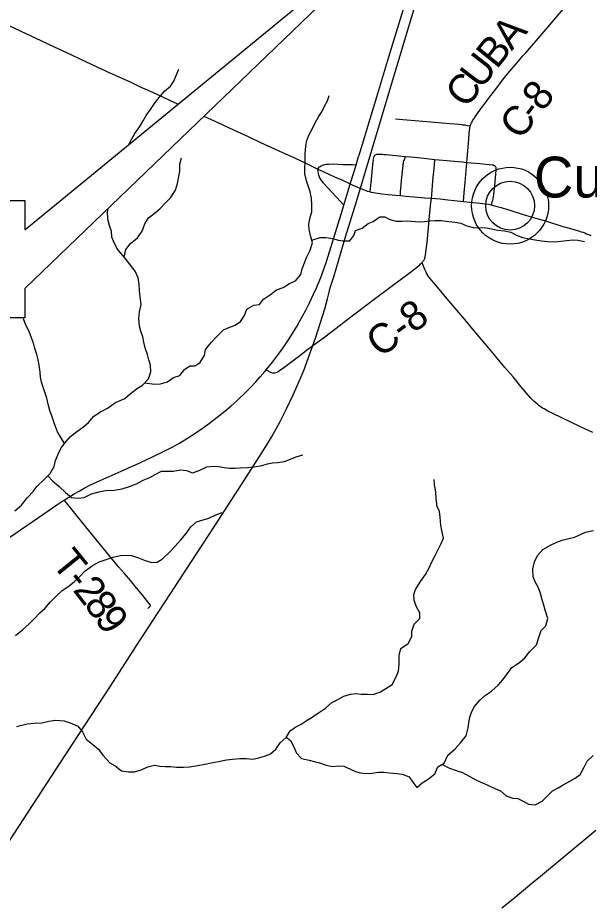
# Model space of a CAD drawing. Extents: x 0 to 34, y 0 to 22.
# Drawn here: x 4.732 to 5.838, y 15.651 to 17.368 of the extents above; entities that cross this region are included whole.
import ezdxf

# ---------------------------------------------------------------- set-up
doc = ezdxf.new("R2010")
doc.units = 0
for name, color, linetype in [('GM_X_County_Road', 7, 'Continuous'), ('GM_X_County_Road_Text', 7, 'Continuous'), ('GM_X_Minor_River', 7, 'Continuous'), ('GM_X_Rail_Line', 7, 'Continuous'), ('GM_X_State_Route', 7, 'Continuous'), ('GM_X_Township_Road', 7, 'Continuous'), ('GM_X_Township_Road_Text', 7, 'Continuous'), ('GM_X_Unincorporated', 7, 'Continuous'), ('GM_X_Unincorporated_Location', 7, 'Continuous'), ('GM_X_Unincorporated_Text', 7, 'Continuous'), ('GM_X_US_Route', 7, 'Continuous'), ('SH_Text', 7, 'Continuous')]:
    doc.layers.add(name, color=color, linetype=linetype)

msp = doc.modelspace()

# ---------------------------------------------------------------- linework, layer by layer
at = {"layer": 'GM_X_County_Road'}
for points in [[(5.6077, 17.1586), (5.608, 17.1598), (5.6085, 17.161), (5.609, 17.1621), (5.6095, 17.1632), (5.6101, 17.1646), (5.6111, 17.1662), (5.6122, 17.1683), (5.6133, 17.1699), (5.6146, 17.172), (5.6157, 17.1737), (5.6167, 17.1751), (5.6265, 17.1887), (5.6476, 17.2172), (5.6588, 17.2321), (5.674, 17.2518), (5.6842, 17.2642), (5.6962, 17.2783), (5.7097, 17.2937), (5.7151, 17.2997), (5.7466, 17.3365), (5.7884, 17.3849)], [(5.601, 17.0878), (5.6047, 17.1322), (5.6057, 17.1441), (5.6069, 17.1534), (5.6071, 17.1553), (5.6074, 17.1572), (5.6077, 17.1586)], [(5.5943, 17.0123), (5.5958, 17.0291), (5.5977, 17.0488), (5.601, 17.0878)], [(5.5143, 16.8938), (5.5153, 16.8952), (5.5164, 16.8967), (5.5174, 16.8982), (5.5184, 16.8995), (5.519, 16.9008), (5.5197, 16.9025), (5.5202, 16.9042), (5.5205, 16.9058), (5.5209, 16.908), (5.5225, 16.9192), (5.5242, 16.9328), (5.5295, 16.9909), (5.5314, 17.0096), (5.5325, 17.0184)], [(5.5325, 17.0184), (5.5496, 17.0171), (5.5644, 17.0157), (5.5885, 17.0128), (5.5943, 17.0123)], [(5.2129, 16.6865), (5.2213, 16.6819), (5.2231, 16.6812), (5.2251, 16.6807), (5.2271, 16.6806), (5.2298, 16.6808), (5.2323, 16.6815), (5.2352, 16.6828), (5.2394, 16.6855), (5.244, 16.6888), (5.2495, 16.6929), (5.2575, 16.699), (5.2753, 16.7125), (5.2936, 16.7265), (5.3021, 16.7327), (5.326, 16.7506), (5.3479, 16.7671), (5.3681, 16.7825), (5.4241, 16.8249), (5.4774, 16.8646), (5.4894, 16.8736), (5.5027, 16.8838), (5.51, 16.8897), (5.5117, 16.8913), (5.5133, 16.8927), (5.5143, 16.8938)], [(5.8446, 16.5652), (5.8199, 16.577), (5.7676, 16.6017), (5.7576, 16.6068), (5.7505, 16.6108), (5.7476, 16.6126), (5.7447, 16.6144), (5.7412, 16.617), (5.7382, 16.6193), (5.7349, 16.6222), (5.7316, 16.6251), (5.7283, 16.6284), (5.725, 16.6318), (5.7167, 16.6411), (5.7055, 16.6544), (5.6904, 16.6726), (5.6748, 16.6911), (5.6566, 16.7131), (5.6437, 16.7283), (5.6185, 16.7582), (5.5969, 16.7839), (5.574, 16.811), (5.5633, 16.8238), (5.544, 16.8465), (5.5332, 16.8594), (5.5269, 16.8672), (5.5248, 16.8703), (5.523, 16.8737), (5.5215, 16.8769), (5.5199, 16.8805), (5.5143, 16.8938)]]:
    msp.add_lwpolyline(points, dxfattribs=at)
at = {"layer": 'GM_X_Minor_River'}
for points in [[(4.9475, 17.1231), (4.9495, 17.1279), (4.9584, 17.1437), (4.9685, 17.1572), (4.9747, 17.1685), (4.9805, 17.1787), (4.9891, 17.1904), (4.998, 17.2035), (5.0057, 17.2133), (5.0169, 17.2261), (5.0276, 17.2354), (5.0338, 17.2452), (5.0385, 17.2558), (5.0437, 17.2682)], [(4.9776, 16.6613), (4.9963, 16.6588), (5.0081, 16.6591), (5.0218, 16.6631), (5.0333, 16.6713), (5.0455, 16.6753), (5.0548, 16.6873), (5.0652, 16.694), (5.0747, 16.6943), (5.0842, 16.7002), (5.0932, 16.7145), (5.0956, 16.7259), (5.1072, 16.7398), (5.1168, 16.7503), (5.1299, 16.7638), (5.1421, 16.7689), (5.1528, 16.773), (5.1628, 16.7797), (5.1705, 16.7913), (5.1753, 16.8038), (5.1887, 16.8116), (5.1997, 16.8126), (5.2074, 16.8235), (5.2212, 16.8321), (5.2328, 16.8414), (5.2454, 16.8458), (5.2576, 16.8532), (5.2694, 16.8584), (5.2795, 16.8708), (5.2827, 16.8821), (5.287, 16.8938), (5.2906, 16.904), (5.298, 16.918), (5.3024, 16.9324), (5.2991, 16.9438), (5.2962, 16.9579), (5.2956, 16.9685), (5.2981, 16.981), (5.3013, 16.992), (5.3014, 17.0056), (5.3005, 17.0182), (5.2976, 17.0311), (5.2947, 17.0406), (5.291, 17.0521), (5.2874, 17.0654), (5.2876, 17.0768), (5.2881, 17.0882), (5.2879, 17.1037), (5.2893, 17.1197), (5.2913, 17.1303), (5.2953, 17.1405), (5.3031, 17.1544), (5.3078, 17.1642), (5.314, 17.1759), (5.3202, 17.1857), (5.3257, 17.1966), (5.3311, 17.2068), (5.3347, 17.2174)], [(4.938, 16.9043), (4.9413, 16.9192), (4.9502, 16.9308), (4.964, 16.9417), (4.9726, 16.9549), (4.9777, 16.9688), (4.9851, 16.9805), (4.9951, 16.9883), (5.007, 16.9981), (5.0178, 17.0097), (5.0274, 17.019), (5.0375, 17.0341), (5.0414, 17.047), (5.0431, 17.0576), (5.0456, 17.0708), (5.0457, 17.0841), (5.0486, 17.0966)], [(4.9065, 16.9987), (4.9049, 16.9923), (4.9058, 16.9786), (4.9091, 16.9664), (4.9127, 16.955), (4.9137, 16.9436), (4.9188, 16.9317), (4.9243, 16.9203)], [(5.3009, 16.9374), (5.3173, 16.9424), (5.3279, 16.9427), (5.342, 16.9406), (5.3518, 16.9374), (5.3613, 16.9358), (5.3749, 16.936), (5.3823, 16.9461), (5.3859, 16.956), (5.3988, 16.9603), (5.4103, 16.9693), (5.4199, 16.9734), (5.4329, 16.9823), (5.4424, 16.9822), (5.4522, 16.9775), (5.464, 16.9743), (5.4757, 16.9741), (5.4856, 16.9748), (5.5091, 16.973), (5.519, 16.9736), (5.5293, 16.9746), (5.5396, 16.9752), (5.5513, 16.9754), (5.5665, 16.9734), (5.5779, 16.9721), (5.5892, 16.97), (5.601, 16.9653), (5.6157, 16.9613), (5.6286, 16.9619), (5.6389, 16.961), (5.6487, 16.9594), (5.6601, 16.9566), (5.6738, 16.9553), (5.6863, 16.9528), (5.6972, 16.947), (5.7085, 16.9423), (5.7225, 16.9398), (5.7331, 16.9378), (5.7453, 16.9361), (5.7574, 16.9348), (5.7707, 16.9343), (5.7943, 16.937), (5.8057, 16.938), (5.8156, 16.9371), (5.8288, 16.9347)], [(4.9209, 16.623), (4.9394, 16.6311), (4.9493, 16.6397), (4.9639, 16.6513), (4.9735, 16.6569), (4.9847, 16.6689), (4.9894, 16.6828), (4.9888, 16.6954), (4.9859, 16.7057), (4.983, 16.7163), (4.9787, 16.7289), (4.9761, 16.7403), (4.974, 16.7506), (4.97, 16.7613), (4.9674, 16.7712), (4.9665, 16.7856), (4.9674, 16.7985), (4.971, 16.8129), (4.969, 16.827), (4.9676, 16.8399), (4.967, 16.8513), (4.9649, 16.8642), (4.9594, 16.8772), (4.9504, 16.8891), (4.9418, 16.8998), (4.9243, 16.9203)], [(4.8227, 16.5437), (4.8166, 16.5535), (4.8092, 16.5665), (4.8034, 16.5818), (4.7986, 16.5955), (4.7943, 16.6077), (4.7914, 16.6176), (4.7882, 16.6317), (4.7849, 16.6412), (4.7813, 16.6527), (4.778, 16.6626), (4.7762, 16.6721), (4.7752, 16.682), (4.7735, 16.6957), (4.7718, 16.7059), (4.7689, 16.7162), (4.7653, 16.7277), (4.7624, 16.7383), (4.7588, 16.7483), (4.754, 16.7605), (4.7477, 16.7727), (4.743, 16.7849)], [(4.7262, 16.4139), (4.7393, 16.4247), (4.7501, 16.4386), (4.7617, 16.4513), (4.7698, 16.4611), (4.7832, 16.4742), (4.7948, 16.4858), (4.8025, 16.4994), (4.805, 16.5111), (4.8105, 16.5232), (4.8163, 16.5353), (4.8256, 16.5477), (4.8341, 16.5574), (4.8464, 16.5671), (4.859, 16.5764), (4.8686, 16.5843), (4.8794, 16.5967), (4.8924, 16.6052), (4.9054, 16.6123), (4.9209, 16.623)], [(4.9183, 16.4534), (4.934, 16.4562), (4.9485, 16.4609), (4.9618, 16.4661), (4.9748, 16.4727), (4.9874, 16.4783), (4.9978, 16.4842), (5.0104, 16.4901), (5.0214, 16.4904), (5.0328, 16.4906), (5.0469, 16.4927), (5.0586, 16.4914), (5.07, 16.4874), (5.0833, 16.4914), (5.0979, 16.4988), (5.1112, 16.5002), (5.121, 16.4997), (5.1316, 16.4977), (5.1419, 16.496), (5.1525, 16.4962), (5.1624, 16.4969), (5.1768, 16.4974), (5.1886, 16.4988), (5.202, 16.5009), (5.2153, 16.5045), (5.2252, 16.5063), (5.2347, 16.5069), (5.248, 16.5091), (5.2599, 16.5138), (5.2706, 16.5182), (5.2835, 16.5219)], [(4.7904, 16.4814), (4.7999, 16.4709), (4.8122, 16.4605), (4.8242, 16.449), (4.8362, 16.4397), (4.8491, 16.4384), (4.8608, 16.4397), (4.875, 16.4468), (4.8887, 16.4504), (4.902, 16.4529), (4.9183, 16.4534)], [(4.9103, 15.9258), (4.9207, 15.9204), (4.9327, 15.9103), (4.9463, 15.9086), (4.9577, 15.9085), (4.9711, 15.9125), (4.9837, 15.9184), (4.9963, 15.9213), (5.0069, 15.9196), (5.0171, 15.9191), (5.0278, 15.919), (5.0391, 15.9177), (5.0528, 15.9179), (5.0642, 15.9185), (5.0802, 15.9206), (5.0939, 15.9234), (5.1061, 15.9259), (5.1202, 15.9288), (5.1362, 15.932), (5.1476, 15.9334), (5.1617, 15.9347), (5.1746, 15.9345), (5.186, 15.9329), (5.1959, 15.935), (5.2096, 15.939), (5.2214, 15.9434), (5.2314, 15.9524), (5.2396, 15.9648), (5.2511, 15.9753), (5.2592, 15.9881), (5.27, 15.9955), (5.2803, 16.0007), (5.2903, 16.0071), (5.3037, 16.0156), (5.3159, 16.0238), (5.3274, 16.032), (5.3401, 16.0425), (5.3512, 16.0488), (5.3627, 16.0551), (5.3757, 16.0587), (5.3871, 16.0605), (5.3966, 16.0592), (5.4091, 16.0587), (5.4201, 16.0581), (5.4342, 16.0633), (5.4442, 16.07), (5.4568, 16.0778), (5.4642, 16.0925), (5.4689, 16.1034), (5.4699, 16.1179), (5.4701, 16.1338), (5.4733, 16.1474), (5.4875, 16.1571), (5.4949, 16.1707), (5.4947, 16.1809), (5.499, 16.1942), (5.5102, 16.205), (5.5103, 16.216), (5.5033, 16.2294), (5.4989, 16.2408), (5.4983, 16.2515), (5.5018, 16.2617), (5.5115, 16.2771), (5.5212, 16.2907), (5.5279, 16.3035), (5.5337, 16.3163), (5.5403, 16.3284), (5.5458, 16.3386), (5.5513, 16.3502), (5.556, 16.3608), (5.5524, 16.3753), (5.5506, 16.3856), (5.5497, 16.4011), (5.5479, 16.4122), (5.5439, 16.4221), (5.5418, 16.4369), (5.5408, 16.4506), (5.5384, 16.4639), (5.5381, 16.4742)], [(4.9164, 16.3243), (4.9311, 16.3275), (4.9429, 16.3281), (4.9523, 16.3269), (4.9656, 16.3229), (4.9784, 16.3178), (4.9913, 16.3135), (5.0016, 16.3145), (5.0123, 16.3208), (5.0269, 16.335), (5.0361, 16.3448), (5.0477, 16.3575), (5.0578, 16.3695), (5.0667, 16.3827), (5.0778, 16.3921), (5.0908, 16.3964), (5.1015, 16.3997), (5.1156, 16.406), (5.1278, 16.4104)], [(5.2515, 15.976), (5.2598, 15.9695), (5.2664, 15.9569), (5.2716, 15.9447), (5.2813, 15.9347), (5.2957, 15.9314), (5.3059, 15.9287), (5.3158, 15.9259), (5.3267, 15.9219), (5.3404, 15.9191), (5.3529, 15.9201), (5.3628, 15.9196), (5.3756, 15.9137), (5.3854, 15.909), (5.3953, 15.9066), (5.4051, 15.9057), (5.4169, 15.906), (5.4298, 15.9077), (5.4405, 15.9079), (5.4515, 15.907), (5.4659, 15.9053), (5.4761, 15.9044), (5.4894, 15.8989), (5.4964, 15.8886), (5.5043, 15.8783), (5.5146, 15.8872), (5.5261, 15.8947), (5.5388, 15.9048), (5.5451, 15.918), (5.5569, 15.9254), (5.564, 15.9409), (5.5786, 15.9532), (5.589, 15.9648), (5.5998, 15.978), (5.6034, 15.9939), (5.6051, 16.0037), (5.6068, 16.0143), (5.6099, 16.0242), (5.6162, 16.0351), (5.6262, 16.0471), (5.6373, 16.0572), (5.6485, 16.0647), (5.6619, 16.0766), (5.6704, 16.0864), (5.6781, 16.0962), (5.6882, 16.1108), (5.7028, 16.1205), (5.7131, 16.1295), (5.7232, 16.1415), (5.7359, 16.1543), (5.7403, 16.1686), (5.7446, 16.1819), (5.7542, 16.1912), (5.7575, 16.2056), (5.7524, 16.2212), (5.7498, 16.2308), (5.7469, 16.2414), (5.7437, 16.2536), (5.7397, 16.2647), (5.7334, 16.2761), (5.7297, 16.2861), (5.7288, 16.3016), (5.732, 16.3149), (5.7378, 16.3273), (5.7479, 16.3386), (5.7628, 16.3471), (5.7754, 16.353), (5.7853, 16.3567), (5.7987, 16.3603), (5.8093, 16.3629), (5.8212, 16.3676), (5.8307, 16.3724), (5.8464, 16.3757)], [(4.7276, 16.1724), (4.7411, 16.1836), (4.7541, 16.1952), (4.7638, 16.2049), (4.7749, 16.2162), (4.7845, 16.2248), (4.7953, 16.2375), (4.8061, 16.2488), (4.818, 16.2596), (4.8287, 16.2667), (4.8414, 16.2764), (4.851, 16.285), (4.8622, 16.2974), (4.8763, 16.307), (4.8897, 16.3152), (4.8993, 16.3185), (4.9164, 16.3243)], [(4.73, 15.9966), (4.7399, 15.9987), (4.7502, 16.0016), (4.7635, 16.003), (4.7783, 16.0032), (4.792, 16.0064), (4.8053, 16.0089), (4.8219, 16.0075), (4.8333, 16.0035), (4.8483, 15.9969), (4.8573, 15.9858), (4.8646, 15.972), (4.8774, 15.9616), (4.8883, 15.9527), (4.8968, 15.9412), (4.9103, 15.9258)], [(5.5532, 15.9231), (5.5678, 15.9158), (5.5822, 15.9103), (5.5924, 15.9071), (5.6056, 15.9001), (5.6173, 15.8939), (5.6282, 15.8888), (5.6414, 15.8826), (5.655, 15.8763), (5.666, 15.872), (5.6769, 15.862), (5.6901, 15.858), (5.7, 15.8571), (5.7102, 15.8517), (5.7207, 15.8458), (5.7336, 15.8445), (5.7466, 15.852), (5.757, 15.8625), (5.767, 15.8722), (5.7777, 15.8774), (5.7873, 15.8833), (5.8003, 15.8907), (5.811, 15.8967), (5.8206, 15.9038), (5.8284, 15.9177), (5.8339, 15.929), (5.8454, 15.9403)]]:
    msp.add_lwpolyline(points, dxfattribs=at)
at = {"layer": 'GM_X_Rail_Line'}
msp.add_lwpolyline([(4.6156, 15.6215), (4.8241, 15.9416), (4.9114, 16.0746), (4.9613, 16.1518), (5.1119, 16.3828), (5.1792, 16.4864), (5.2122, 16.5384), (5.2228, 16.5564), (5.239, 16.5855), (5.2512, 16.6096), (5.2649, 16.6381), (5.2772, 16.6659), (5.2853, 16.685), (5.2949, 16.71), (5.309, 16.7496), (5.3263, 16.8047), (5.3317, 16.8237), (5.3347, 16.8369), (5.3368, 16.8453), (5.3438, 16.8662), (5.3662, 16.9437), (5.3876, 17.012), (5.4635, 17.2672), (5.5484, 17.5486)], dxfattribs=at)
at = {"layer": 'GM_X_State_Route'}
msp.add_line((5.3754, 17.0462), (5.382, 17.0433), dxfattribs=at)
for points in [[(4.6811, 17.3682), (4.7112, 17.3543), (4.7144, 17.3528), (4.7475, 17.337), (4.7768, 17.3234), (4.8026, 17.3112), (4.8263, 17.3003), (4.8617, 17.2836), (4.8866, 17.2723), (4.9103, 17.2614), (4.9493, 17.2435), (4.9689, 17.2342), (4.9927, 17.2234), (5.0118, 17.2144), (5.0259, 17.208), (5.0422, 17.2007)], [(5.0924, 17.1773), (5.1189, 17.1648), (5.1494, 17.1508), (5.1781, 17.1376), (5.2018, 17.1266), (5.2215, 17.1173), (5.2446, 17.1067), (5.2661, 17.097), (5.2892, 17.0863), (5.3129, 17.0748), (5.324, 17.0698), (5.3449, 17.0601), (5.3591, 17.0538), (5.3754, 17.0462)], [(5.3129, 17.0748), (5.3124, 17.0724), (5.3124, 17.0703), (5.3131, 17.0662), (5.3139, 17.0637), (5.3144, 17.0618), (5.3162, 17.058), (5.3172, 17.0563), (5.3192, 17.0531), (5.323, 17.0482), (5.3322, 17.0383), (5.3568, 17.0121), (5.3631, 17.0053)], [(5.382, 17.0433), (5.3895, 17.0399), (5.3972, 17.0369), (5.4021, 17.0348), (5.4054, 17.0335), (5.4082, 17.0324), (5.4123, 17.0313), (5.4137, 17.0309), (5.4162, 17.0302), (5.4202, 17.0294), (5.4243, 17.0288), (5.4289, 17.0281), (5.4364, 17.0272), (5.4488, 17.0257), (5.4717, 17.0237), (5.4727, 17.0236), (5.4834, 17.0226), (5.4982, 17.0211), (5.5199, 17.0194), (5.5325, 17.0184)], [(5.5325, 17.0184), (5.5496, 17.0171), (5.5644, 17.0157), (5.5885, 17.0128), (5.5943, 17.0123)], [(5.5943, 17.0123), (5.607, 17.0111), (5.6268, 17.009), (5.6358, 17.0077), (5.6427, 17.0068), (5.6482, 17.0057), (5.6489, 17.0055), (5.6548, 17.004), (5.6619, 17.0021), (5.6682, 17.0003)], [(5.6682, 17.0003), (5.6691, 17.0001), (5.6786, 16.9973), (5.694, 16.9924), (5.7165, 16.9852), (5.7391, 16.9786), (5.7552, 16.9738), (5.7866, 16.9638), (5.8016, 16.9597), (5.8171, 16.9554), (5.8223, 16.9537), (5.8259, 16.9526), (5.8292, 16.9513), (5.8328, 16.9499), (5.8364, 16.9483), (5.8407, 16.9463)]]:
    msp.add_lwpolyline(points, dxfattribs=at)
at = {"layer": 'GM_X_Township_Road'}
for points in [[(5.4631, 17.1723), (5.4773, 17.1711), (5.5311, 17.1666), (5.5601, 17.1639), (5.5854, 17.1616), (5.5912, 17.1611), (5.5932, 17.1608), (5.5952, 17.1606), (5.5971, 17.1603), (5.5993, 17.16), (5.602, 17.1595), (5.6077, 17.1586)], [(5.4233, 17.1017), (5.4242, 17.1025), (5.4254, 17.1032), (5.4267, 17.1036), (5.4308, 17.1038), (5.4338, 17.1038), (5.4376, 17.1037), (5.4413, 17.1034), (5.445, 17.1031), (5.4823, 17.0994)], [(5.4137, 17.0309), (5.4144, 17.0375), (5.4165, 17.0553), (5.4191, 17.0837), (5.4203, 17.093), (5.4211, 17.0979), (5.4214, 17.0989), (5.4218, 17.0998), (5.4226, 17.1008), (5.4233, 17.1017)], [(5.4727, 17.0236), (5.4728, 17.0261), (5.4728, 17.0287), (5.4729, 17.0328), (5.473, 17.0361), (5.4744, 17.0527), (5.4778, 17.0816), (5.4781, 17.0838), (5.4784, 17.0859), (5.4788, 17.0883), (5.4793, 17.0907), (5.4801, 17.093), (5.4823, 17.0994)], [(5.4823, 17.0994), (5.4925, 17.0984), (5.5054, 17.0971), (5.5184, 17.0957), (5.5391, 17.0937)], [(5.5325, 17.0184), (5.5331, 17.0251), (5.5355, 17.0522), (5.5382, 17.0826), (5.5391, 17.0937)], [(5.5391, 17.0937), (5.5925, 17.0886), (5.601, 17.0878)], [(5.601, 17.0878), (5.6265, 17.0855), (5.6499, 17.0831), (5.6517, 17.0828), (5.6528, 17.0825), (5.6536, 17.0821), (5.6544, 17.0817)], [(5.6489, 17.0055), (5.6503, 17.0115), (5.6511, 17.0148), (5.6517, 17.0175), (5.6524, 17.0219), (5.653, 17.0255), (5.6551, 17.0433), (5.6577, 17.0729), (5.6578, 17.076), (5.6577, 17.0769), (5.6575, 17.0779), (5.6571, 17.0789), (5.6567, 17.0796), (5.6559, 17.0806), (5.6552, 17.0812), (5.6544, 17.0817)], [(4.9839, 16.2249), (4.9879, 16.2283), (4.9885, 16.229), (4.9889, 16.2296), (4.9889, 16.2307), (4.9886, 16.2313), (4.9881, 16.2319), (4.9856, 16.2353), (4.9738, 16.2497), (4.9647, 16.2607), (4.9628, 16.2631), (4.9623, 16.2636), (4.9505, 16.278), (4.9383, 16.2921), (4.9271, 16.3054), (4.9039, 16.3338), (4.8639, 16.3828), (4.8262, 16.429), (4.8217, 16.4345)], [(5.6689, 15.6452), (5.6904, 15.6628), (5.7271, 15.6935), (5.7434, 15.7069), (5.7894, 15.745), (5.8508, 15.7955)]]:
    msp.add_lwpolyline(points, dxfattribs=at)
at = {"layer": 'GM_X_Unincorporated'}
for radius in [0.0744, 0.0472]:
    msp.add_circle((5.6848, 17.004), radius, dxfattribs=at)
at = {"layer": 'GM_X_Unincorporated_Location'}
msp.add_line((5.6848, 17.004), (5.6848, 17.004), dxfattribs=at)
at = {"layer": 'GM_X_US_Route'}
for points in [[(5.3925, 17.1018), (5.4267, 17.2149), (5.4502, 17.2922), (5.4699, 17.357), (5.4849, 17.4063)], [(5.1616, 16.632), (5.1695, 16.6394), (5.1823, 16.6521), (5.193, 16.6634), (5.2013, 16.6726), (5.211, 16.6841), (5.2129, 16.6865), (5.2249, 16.7016), (5.2344, 16.7139), (5.2453, 16.7291), (5.2559, 16.7445), (5.2606, 16.7518), (5.2719, 16.7704), (5.2806, 16.7855), (5.2889, 16.8008), (5.2968, 16.8163), (5.3045, 16.8327), (5.3105, 16.8464), (5.3123, 16.8503), (5.3134, 16.8531), (5.3183, 16.8653), (5.3241, 16.8811), (5.3299, 16.8982), (5.3413, 16.9337), (5.3604, 16.9961), (5.3631, 17.0053), (5.3746, 17.0437), (5.3754, 17.0462), (5.3835, 17.0722), (5.3868, 17.0832), (5.3916, 17.099), (5.3925, 17.1018)], [(5.3129, 17.0748), (5.3141, 17.0769), (5.3151, 17.0783), (5.3161, 17.0793), (5.3173, 17.0801), (5.3191, 17.0811), (5.3215, 17.0822), (5.3246, 17.0831), (5.3264, 17.0836), (5.3288, 17.0841), (5.3303, 17.0843), (5.3337, 17.0847), (5.3423, 17.0849), (5.3614, 17.084), (5.3799, 17.0835), (5.3868, 17.0832)], [(4.952, 16.4993), (4.9584, 16.5022), (4.9929, 16.5181), (5.0153, 16.5289), (5.0308, 16.5369), (5.0449, 16.5448), (5.0555, 16.5512), (5.0728, 16.5623), (5.0893, 16.5735), (5.1029, 16.5833), (5.1178, 16.5946), (5.1324, 16.6062), (5.1452, 16.617), (5.1559, 16.6266), (5.1616, 16.632)], [(4.6589, 16.3223), (4.6622, 16.3246), (4.7045, 16.3541), (4.7822, 16.4079), (4.8075, 16.425), (4.8192, 16.4329), (4.8217, 16.4345), (4.8306, 16.4403), (4.8413, 16.4467), (4.8507, 16.4519), (4.8608, 16.4575), (4.8729, 16.4638), (4.8914, 16.4725), (4.9318, 16.4902), (4.952, 16.4993)]]:
    msp.add_lwpolyline(points, dxfattribs=at)
at = {"layer": 'SH_Text'}
msp.add_lwpolyline([(3.596, 17.0143), (4.7456, 17.0143), (4.7456, 16.9576), (5.5484, 17.6156), (4.7456, 16.844), (4.7456, 16.7873), (3.596, 16.7873)], close=True, dxfattribs=at)

# ---------------------------------------------------------------- texts
at = {"layer": 'GM_X_County_Road_Text'}
for s, height, rotation, p in [('A', 0.0568, 49.3315, (5.6878, 17.3026)), ('B', 0.0568, 51.1244, (5.6588, 17.2666)), ('U', 0.0568, 52.3483, (5.6285, 17.2273)), ('C', 0.0568, 52.4393, (5.6001, 17.1903)), ('8', 0.0568, 51.3573, (5.7475, 17.1843)), ('C', 0.0568, 52.5118, (5.7051, 17.129)), ('-', 0.0568, 52.3729, (5.7334, 17.166)), ('C-8', 0.05682, 36.597, (5.4334, 16.7084))]:
    msp.add_text(s, height=height, rotation=rotation, dxfattribs=at).set_placement(p)
at = {"layer": 'GM_X_Township_Road_Text'}
for s, rotation, p in [('T', 309.1136, (4.7961, 16.311)), ('-', 308.75, (4.8228, 16.2781)), ('2', 307.765, (4.8373, 16.2601)), ('8', 306.4651, (4.8585, 16.2327)), ('9', 305.0773, (4.8791, 16.2049))]:
    msp.add_text(s, height=0.0568, rotation=rotation, dxfattribs=at).set_placement(p)
at = {"layer": 'GM_X_Unincorporated_Text'}
msp.add_text('Cuba', height=0.07898, rotation=0, dxfattribs=at).set_placement((5.7309, 17.0199))

doc.saveas('drawing.dxf')
